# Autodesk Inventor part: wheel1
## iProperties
Created: 2002-07
Part Number: wheel1
Document SubType Name: Modeling
Designer: Administrator
Control State: 0
Master: False
Checked Out: False
Shininess: 64.0
Length Units: 11269
Angle Units: 11279
Time Units: 11290
Mass Units: 11283
Length Display Precision: 3
Angle Display Precision: 2
Density: 0.0
Volumn: 0.0
Area: 0.0
PropertySet Name: Model Information
Author: Administrator
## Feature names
1. Revolution1
2. Extrusion1
3. Circular Pattern1
4. Extrusion2
